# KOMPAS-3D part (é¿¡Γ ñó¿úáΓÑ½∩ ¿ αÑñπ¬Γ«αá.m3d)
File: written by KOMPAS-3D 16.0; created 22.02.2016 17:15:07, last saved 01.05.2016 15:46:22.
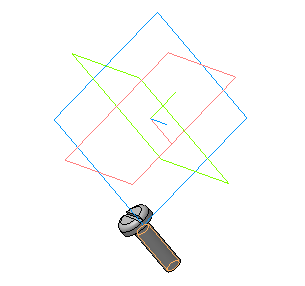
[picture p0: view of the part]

Referenced files in E:\Libs\PartLib\DATA\vault\Methods\Kompas\3D\: PLib_Screw_ISO_1207_1500.m3d
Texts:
  Винт с плоской головкой ГОСТ Р ИСО 1580 - М6 x 20
  (-) Винт с плоской головкой ГОСТ Р ИСО 1580 - М6 x 20
  Винт с плоской головкой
